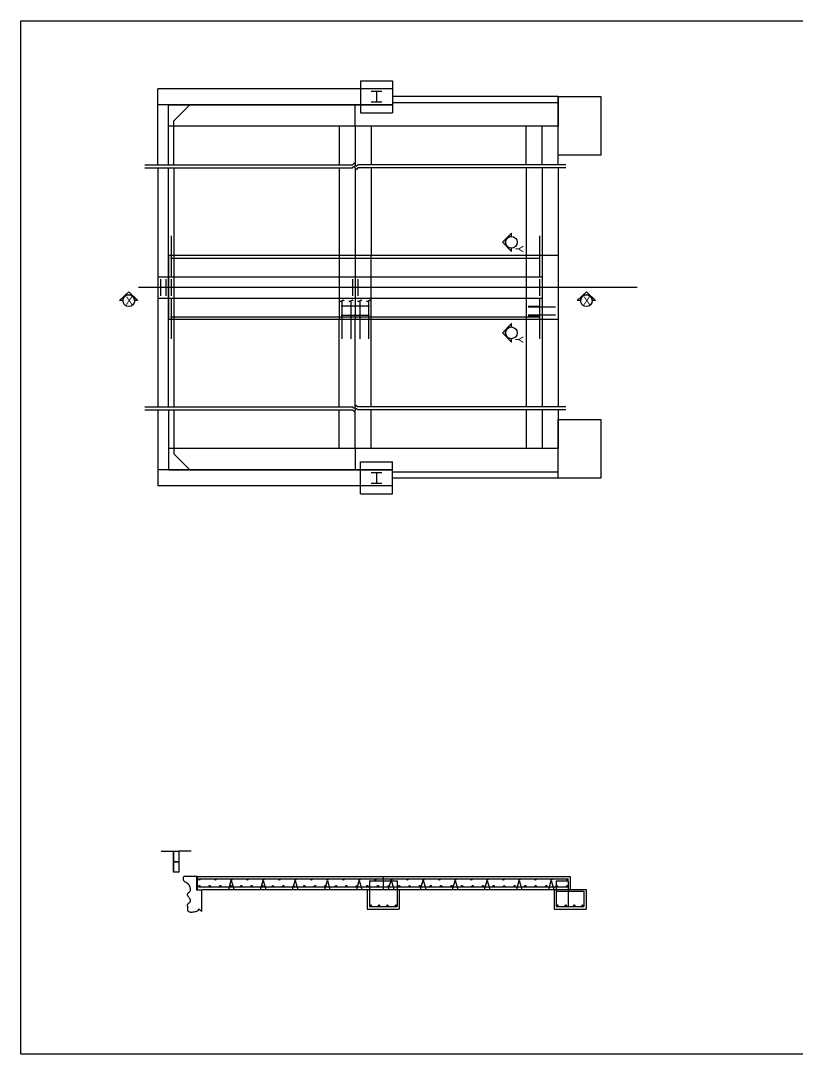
# Model space of a CAD drawing. Extents: x 1531 to 2925, y 1224 to 1658.
# Drawn here: x 2196.7 to 2269.3, y 1331.8 to 1428.7 of the extents above; entities that cross this region are included whole.
import ezdxf

# ---------------------------------------------------------------- set-up
doc = ezdxf.new("R2010")
doc.units = 0
for name, color, linetype in [('B_Border', 7, 'Continuous'), ('BD-EXIST-COSS', 7, 'Continuous'), ('BD-PROP-COSS', 7, 'Continuous'), ('BD-PROP-OSB', 7, 'Continuous'), ('D_FEMA A', 7, 'Continuous'), ('R_Border Prem', 7, 'Continuous'), ('R_Draft', 7, 'Continuous'), ('R_Guard Rail', 7, 'Continuous'), ('R_Road Edge of Shoulder', 7, 'Continuous'), ('R_Survey Control', 7, 'Continuous'), ('R_Wall', 7, 'Continuous')]:
    doc.layers.add(name, color=color, linetype=linetype)

msp = doc.modelspace()

# ---------------------------------------------------------------- linework, layer by layer
at = {"layer": 'B_Border'}
msp.add_line((2254.494, 1403.73), (2207.761, 1403.73), dxfattribs=at)
at = {"layer": 'BD-EXIST-COSS'}
for p, q in [((2210.833, 1408.563), (2210.833, 1404.73)), ((2245.333, 1408.563), (2245.333, 1404.73)), ((2210.75, 1406.48), (2245.417, 1406.48)), ((2209.833, 1404.511), (2209.833, 1402.949)), ((2210.333, 1404.511), (2210.333, 1402.949)), ((2210.833, 1404.511), (2210.833, 1402.949)), ((2227.833, 1404.511), (2227.833, 1402.949)), ((2228.333, 1404.511), (2228.333, 1402.949)), ((2245.333, 1404.511), (2245.333, 1402.949)), ((2210.833, 1402.73), (2210.833, 1398.897)), ((2226.833, 1402.465), (2226.833, 1398.897)), ((2227.667, 1402.465), (2227.667, 1398.897)), ((2228.5, 1402.465), (2228.5, 1398.897)), ((2229.333, 1402.465), (2229.333, 1398.897)), ((2245.333, 1402.73), (2245.333, 1398.897)), ((2229.417, 1401.98), (2226.75, 1401.98)), ((2244.292, 1401.98), (2245.375, 1401.98)), ((2244.292, 1401.897), (2246.833, 1401.897)), ((2244.292, 1401.164), (2246.833, 1401.164)), ((2210.75, 1400.98), (2245.417, 1400.98)), ((2229.417, 1401.08), (2226.75, 1401.08)), ((2244.292, 1401.08), (2245.375, 1401.08)), ((2213.373, 1348.288), (2248.039, 1348.288)), ((2229.414, 1348.108), (2231.998, 1348.108)), ((2229.414, 1348.108), (2229.414, 1345.705)), ((2231.998, 1348.108), (2231.998, 1345.705)), ((2246.914, 1348.108), (2248.025, 1348.108)), ((2246.914, 1348.108), (2246.914, 1345.702)), ((2248.025, 1348.108), (2248.025, 1345.702)), ((2213.373, 1347.538), (2248.039, 1347.538)), ((2246.914, 1347.121), (2249.498, 1347.121)), ((2249.498, 1347.121), (2249.498, 1345.705)), ((2229.414, 1345.705), (2231.998, 1345.705)), ((2246.914, 1345.705), (2249.498, 1345.705))]:
    msp.add_line(p, q, dxfattribs=at)
for centre, radius in [((2213.449, 1348.225), 0.063), ((2214.949, 1348.225), 0.063), ((2216.449, 1348.225), 0.063), ((2217.949, 1348.225), 0.063), ((2219.449, 1348.225), 0.063), ((2220.949, 1348.225), 0.063), ((2222.449, 1348.225), 0.063), ((2223.949, 1348.225), 0.063), ((2225.449, 1348.225), 0.063), ((2226.949, 1348.225), 0.063), ((2228.449, 1348.225), 0.063), ((2229.949, 1348.225), 0.063), ((2231.449, 1348.225), 0.063), ((2232.949, 1348.225), 0.063), ((2234.449, 1348.225), 0.063), ((2235.949, 1348.225), 0.063), ((2237.449, 1348.225), 0.063), ((2238.949, 1348.225), 0.063), ((2240.449, 1348.225), 0.063), ((2241.949, 1348.225), 0.063), ((2243.449, 1348.225), 0.063), ((2244.949, 1348.225), 0.063), ((2246.449, 1348.225), 0.063), ((2247.949, 1348.225), 0.063), ((2213.449, 1347.601), 0.063), ((2214.435, 1347.601), 0.063), ((2215.421, 1347.601), 0.063), ((2216.406, 1347.601), 0.063), ((2217.392, 1347.601), 0.063), ((2218.378, 1347.601), 0.063), ((2219.363, 1347.601), 0.063), ((2220.349, 1347.601), 0.063), ((2221.335, 1347.601), 0.063), ((2222.321, 1347.601), 0.063), ((2223.306, 1347.601), 0.063), ((2224.292, 1347.601), 0.063), ((2225.278, 1347.601), 0.063), ((2226.263, 1347.601), 0.063), ((2227.249, 1347.601), 0.063), ((2228.235, 1347.601), 0.063), ((2229.22, 1347.601), 0.063), ((2230.206, 1347.601), 0.063), ((2231.192, 1347.601), 0.063), ((2232.178, 1347.601), 0.063), ((2233.163, 1347.601), 0.063), ((2234.149, 1347.601), 0.063), ((2235.135, 1347.601), 0.063), ((2236.12, 1347.601), 0.063), ((2237.106, 1347.601), 0.063), ((2238.092, 1347.601), 0.063), ((2239.078, 1347.601), 0.063), ((2240.063, 1347.601), 0.063), ((2241.049, 1347.601), 0.063), ((2242.035, 1347.601), 0.063), ((2243.02, 1347.601), 0.063), ((2244.006, 1347.601), 0.063), ((2244.992, 1347.601), 0.063), ((2245.978, 1347.601), 0.063), ((2246.963, 1347.601), 0.063), ((2247.949, 1347.601), 0.063), ((2229.522, 1345.77), 0.0625), ((2230.311, 1345.77), 0.0625), ((2231.101, 1345.77), 0.0625), ((2231.89, 1345.77), 0.0625), ((2247.022, 1345.77), 0.0625), ((2247.811, 1345.77), 0.0625), ((2248.601, 1345.77), 0.0625), ((2249.39, 1345.77), 0.0625)]:
    msp.add_circle(centre, radius, dxfattribs=at)
for centre, start, end in [((2226.741, 1402.519), 185.21332, 329.73936), ((2226.926, 1402.411), 5.21239, 149.73919), ((2227.574, 1402.519), 185.21332, 329.73936), ((2227.759, 1402.411), 5.21239, 149.73919), ((2228.407, 1402.519), 185.21332, 329.73936), ((2228.593, 1402.411), 5.21239, 149.73919), ((2229.241, 1402.519), 185.21332, 329.73936), ((2229.426, 1402.411), 5.21239, 149.73919)]:
    msp.add_arc(centre, 0.107, start, end, dxfattribs=at)
at = {"layer": 'BD-PROP-COSS'}
for p, q in [((2211.037, 1350.873), (2211.537, 1350.873)), ((2213.248, 1348.496), (2213.206, 1348.496)), ((2230.706, 1348.496), (2230.706, 1347.288))]:
    msp.add_line(p, q, dxfattribs=at)
at = {"layer": 'BD-PROP-OSB'}
for p, q in [((2211.037, 1349.873), (2211.037, 1350.873)), ((2211.037, 1350.873), (2211.537, 1350.873)), ((2211.537, 1350.873), (2211.537, 1350.873)), ((2211.537, 1350.873), (2211.537, 1349.873)), ((2211.537, 1349.873), (2211.037, 1349.873)), ((2211.037, 1348.894), (2211.037, 1349.873)), ((2211.037, 1349.873), (2211.537, 1349.873)), ((2211.537, 1349.873), (2211.537, 1349.873)), ((2211.537, 1349.873), (2211.537, 1348.894)), ((2211.537, 1348.894), (2211.037, 1348.894)), ((2213.206, 1348.496), (2213.206, 1348.496)), ((2213.206, 1348.496), (2213.206, 1348.413)), ((2213.248, 1348.496), (2213.206, 1348.496)), ((2213.206, 1348.413), (2213.206, 1348.413)), ((2213.206, 1348.413), (2213.248, 1348.413)), ((2213.248, 1348.413), (2213.206, 1348.413)), ((2213.206, 1348.413), (2213.206, 1348.413)), ((2213.206, 1348.413), (2213.206, 1347.246)), ((2213.248, 1348.413), (2213.248, 1348.496)), ((2213.248, 1347.246), (2213.248, 1348.413)), ((2213.206, 1347.246), (2213.248, 1347.246)), ((2213.206, 1347.246), (2213.206, 1347.246))]:
    msp.add_line(p, q, dxfattribs=at)
at = {"layer": 'D_FEMA A'}
for p, q in [((2216.212, 1347.3), (2216.455, 1348.144)), ((2216.455, 1348.144), (2216.698, 1347.3)), ((2219.206, 1347.292), (2219.449, 1348.137)), ((2219.449, 1348.137), (2219.692, 1347.292)), ((2222.207, 1347.288), (2222.45, 1348.132)), ((2222.45, 1348.132), (2222.693, 1347.288)), ((2225.22, 1347.294), (2225.464, 1348.138)), ((2225.464, 1348.138), (2225.707, 1347.294)), ((2228.214, 1347.278), (2228.457, 1348.123)), ((2228.457, 1348.123), (2228.7, 1347.278)), ((2231.199, 1347.302), (2231.442, 1348.146)), ((2231.442, 1348.146), (2231.685, 1347.302)), ((2234.207, 1347.304), (2234.45, 1348.149)), ((2234.45, 1348.149), (2234.693, 1347.304)), ((2237.197, 1347.283), (2237.44, 1348.128)), ((2237.44, 1348.128), (2237.683, 1347.283)), ((2240.201, 1347.285), (2240.444, 1348.13)), ((2240.444, 1348.13), (2240.687, 1347.285)), ((2243.207, 1347.275), (2243.45, 1348.119)), ((2243.45, 1348.119), (2243.694, 1347.275)), ((2246.211, 1347.295), (2246.454, 1348.14)), ((2246.454, 1348.14), (2246.697, 1347.295))]:
    msp.add_line(p, q, dxfattribs=at)
at = {"layer": 'R_Border Prem'}
for p, q in [((2247.083, 1421.625), (2231.583, 1421.625)), ((2247.083, 1421.042), (2231.583, 1421.042)), ((2247.083, 1418.833), (2210.583, 1418.833)), ((2247.083, 1406.73), (2210.583, 1406.73)), ((2210.583, 1406.73), (2210.583, 1400.73)), ((2226.583, 1406.73), (2226.583, 1400.73)), ((2228.083, 1406.73), (2228.083, 1400.73)), ((2229.583, 1400.73), (2229.583, 1406.73)), ((2244.083, 1406.73), (2244.083, 1400.73)), ((2245.583, 1406.73), (2245.583, 1400.73)), ((2247.083, 1406.73), (2247.083, 1400.73)), ((2247.083, 1400.73), (2210.583, 1400.73)), ((2247.083, 1388.627), (2210.583, 1388.627)), ((2247.083, 1386.418), (2231.583, 1386.418)), ((2247.083, 1385.835), (2231.583, 1385.835)), ((2212.702, 1350.873), (2211.537, 1350.873)), ((2211.537, 1350.873), (2211.537, 1348.894)), ((2213.248, 1348.496), (2248.206, 1348.496)), ((2213.248, 1348.496), (2213.248, 1347.246)), ((2248.206, 1348.496), (2248.206, 1347.288)), ((2213.248, 1347.246), (2213.706, 1347.246)), ((2213.706, 1347.246), (2213.789, 1347.288)), ((2213.789, 1347.288), (2249.706, 1347.288)), ((2229.206, 1347.288), (2229.206, 1345.455)), ((2232.206, 1347.288), (2232.206, 1345.455)), ((2246.706, 1347.288), (2246.706, 1345.455)), ((2249.706, 1347.288), (2249.706, 1345.455)), ((2229.206, 1345.455), (2232.206, 1345.455)), ((2246.706, 1345.455), (2249.706, 1345.455))]:
    msp.add_line(p, q, dxfattribs=at)
for points in [[(2247.083, 1421.625), (2251.083, 1421.625), (2251.083, 1416.125), (2247.083, 1416.125)], [(2247.083, 1391.335), (2251.083, 1391.335), (2251.083, 1385.835), (2247.083, 1385.835)]]:
    msp.add_lwpolyline(points, close=True, dxfattribs=at)
at = {"layer": 'R_Draft'}
for p, q in [((2209.583, 1404.73), (2245.583, 1404.73)), ((2209.583, 1404.73), (2209.583, 1402.73)), ((2245.583, 1404.73), (2245.583, 1402.73)), ((2209.583, 1402.73), (2245.583, 1402.73))]:
    msp.add_line(p, q, dxfattribs=at)
at = {"layer": 'R_Guard Rail'}
for p, q in [((2228.583, 1423.083), (2231.583, 1423.083)), ((2228.583, 1423.083), (2228.583, 1422.333)), ((2231.583, 1423.083), (2231.583, 1422.333)), ((2231.583, 1422.333), (2209.583, 1422.333)), ((2209.583, 1415.226), (2209.583, 1422.333)), ((2228.583, 1422.333), (2228.583, 1420.833)), ((2230.583, 1422.083), (2229.583, 1422.083)), ((2230.083, 1422.083), (2230.083, 1421.083)), ((2231.583, 1422.333), (2231.583, 1420.833)), ((2247.083, 1421.625), (2247.083, 1418.833)), ((2231.583, 1420.833), (2209.583, 1420.833)), ((2210.583, 1420.833), (2231.583, 1420.833)), ((2210.583, 1415.226), (2210.583, 1420.833)), ((2212.583, 1420.833), (2211.083, 1419.333)), ((2228.083, 1418.833), (2228.083, 1420.833)), ((2228.583, 1420.833), (2228.583, 1420.083)), ((2230.583, 1421.083), (2229.583, 1421.083)), ((2231.583, 1420.833), (2231.583, 1420.083)), ((2228.583, 1420.083), (2231.583, 1420.083)), ((2211.083, 1415.226), (2211.083, 1419.333)), ((2226.583, 1418.833), (2226.583, 1415.226)), ((2228.083, 1418.833), (2228.083, 1415.226)), ((2229.583, 1418.833), (2229.583, 1415.226)), ((2244.083, 1415.226), (2244.083, 1418.833)), ((2245.583, 1415.226), (2245.583, 1418.833)), ((2247.083, 1415.226), (2247.083, 1418.833)), ((2209.583, 1414.926), (2209.583, 1392.534)), ((2210.583, 1406.73), (2210.583, 1414.926)), ((2210.583, 1392.534), (2210.583, 1414.926)), ((2211.083, 1414.926), (2211.083, 1392.534)), ((2226.583, 1414.926), (2226.583, 1406.73)), ((2228.083, 1414.926), (2228.083, 1406.73)), ((2229.583, 1414.926), (2229.583, 1406.73)), ((2244.083, 1414.926), (2244.083, 1406.73)), ((2245.583, 1414.926), (2245.583, 1406.73)), ((2247.083, 1414.926), (2247.083, 1406.73)), ((2210.583, 1392.534), (2210.583, 1400.73)), ((2226.583, 1392.534), (2226.583, 1400.73)), ((2228.083, 1392.534), (2228.083, 1400.73)), ((2229.583, 1392.534), (2229.583, 1400.73)), ((2244.083, 1400.73), (2244.083, 1392.534)), ((2245.583, 1400.73), (2245.583, 1392.534)), ((2247.083, 1400.73), (2247.083, 1392.534)), ((2209.583, 1392.234), (2209.583, 1385.127)), ((2210.583, 1392.234), (2210.583, 1386.627)), ((2211.083, 1392.234), (2211.083, 1388.127)), ((2226.583, 1388.627), (2226.583, 1392.234)), ((2228.083, 1388.627), (2228.083, 1392.234)), ((2229.583, 1388.627), (2229.583, 1392.234)), ((2244.083, 1392.234), (2244.083, 1388.627)), ((2245.583, 1392.234), (2245.583, 1388.627)), ((2247.083, 1392.234), (2247.083, 1388.627)), ((2228.083, 1388.627), (2228.083, 1386.627)), ((2247.083, 1385.835), (2247.083, 1388.627)), ((2212.583, 1386.627), (2211.083, 1388.127)), ((2231.583, 1386.627), (2209.583, 1386.627)), ((2210.583, 1386.627), (2231.583, 1386.627)), ((2228.583, 1387.377), (2231.583, 1387.377)), ((2228.583, 1386.627), (2228.583, 1387.377)), ((2228.583, 1385.127), (2228.583, 1386.627)), ((2231.583, 1386.627), (2231.583, 1387.377)), ((2231.583, 1385.127), (2231.583, 1386.627)), ((2229.583, 1386.377), (2230.583, 1386.377)), ((2230.083, 1386.377), (2230.083, 1385.377)), ((2231.583, 1385.127), (2209.583, 1385.127)), ((2228.583, 1384.377), (2228.583, 1385.127)), ((2229.583, 1385.377), (2230.583, 1385.377)), ((2231.583, 1384.377), (2231.583, 1385.127)), ((2228.583, 1384.377), (2231.583, 1384.377))]:
    msp.add_line(p, q, dxfattribs=at)
at = {"layer": 'R_Road Edge of Shoulder'}
for p, q in [((2209.873, 1350.873), (2211.037, 1350.873)), ((2211.037, 1350.873), (2211.037, 1348.894)), ((2213.206, 1348.496), (2212.007, 1348.496)), ((2213.706, 1345.216), (2213.706, 1347.246))]:
    msp.add_line(p, q, dxfattribs=at)
msp.add_open_spline([(2213.706, 1345.216), (2213.366, 1345.517), (2213.354, 1345.208), (2212.347, 1345.095), (2212.403, 1345.671), (2212.302, 1345.861), (2212.754, 1346.263), (2212.221, 1346.825), (2212.725, 1347.171), (2212.459, 1347.846), (2211.903, 1348.078), (2212.007, 1348.496)], degree=2, dxfattribs=at)
at = {"layer": 'R_Survey Control'}
for points in [[(2242.707, 1408.512), (2242.707, 1408.819), (2241.88, 1407.96), (2242.707, 1407.1), (2242.707, 1407.407)], [(2206.295, 1402.486), (2205.987, 1402.486), (2206.847, 1403.313), (2207.707, 1402.486), (2207.399, 1402.486)], [(2249.194, 1402.486), (2248.887, 1402.486), (2249.746, 1403.313), (2250.606, 1402.486), (2250.299, 1402.486)], [(2242.707, 1400.019), (2242.707, 1400.326), (2241.88, 1399.466), (2242.707, 1398.607), (2242.707, 1398.914)]]:
    msp.add_lwpolyline(points, dxfattribs=at)
for centre in [(2242.707, 1407.957), (2206.849, 1402.486), (2249.746, 1402.486), (2242.707, 1399.464)]:
    msp.add_circle(centre, 0.552, dxfattribs=at)
for centre, start, end in [((2242.707, 1407.96), 90, 270), ((2206.847, 1402.486), 0, 180), ((2249.746, 1402.486), 0, 180), ((2242.707, 1399.466), 90, 270)]:
    msp.add_arc(centre, 0.552, start, end, dxfattribs=at)
at = {"layer": 'R_Wall'}
for p, q in [((2208.361, 1415.226), (2227.833, 1415.226)), ((2208.361, 1414.926), (2227.833, 1414.926)), ((2228, 1415.393), (2227.833, 1415.226)), ((2228, 1415.093), (2227.833, 1414.926)), ((2228.167, 1415.06), (2228, 1415.393)), ((2228.167, 1414.76), (2228, 1415.093)), ((2228.333, 1415.226), (2228.167, 1415.06)), ((2228.333, 1414.926), (2228.167, 1414.76)), ((2247.806, 1415.226), (2228.333, 1415.226)), ((2247.806, 1414.926), (2228.333, 1414.926)), ((2208.361, 1392.534), (2227.833, 1392.534)), ((2227.833, 1392.534), (2228, 1392.367)), ((2228.167, 1392.701), (2228, 1392.367)), ((2228, 1392.067), (2228.167, 1392.401)), ((2228.333, 1392.534), (2228.167, 1392.701)), ((2228.333, 1392.234), (2228.167, 1392.401)), ((2247.806, 1392.534), (2228.333, 1392.534)), ((2208.361, 1392.234), (2227.833, 1392.234)), ((2227.833, 1392.234), (2228, 1392.067)), ((2247.806, 1392.234), (2228.333, 1392.234))]:
    msp.add_line(p, q, dxfattribs=at)
msp.add_lwpolyline([(2196.716, 1428.728), (2341.933, 1428.728), (2341.933, 1331.833), (2196.716, 1331.833)], close=True, dxfattribs=at)

# ---------------------------------------------------------------- texts
at = {"layer": 'R_Survey Control'}
for s, rotation, p in [('Y', 270, (2243.082, 1407.662)), ('X', 360, (2206.552, 1402.111)), ('X', 360, (2249.449, 1402.111)), ('Y', 270, (2243.082, 1399.168))]:
    msp.add_text(s, height=0.75, rotation=rotation, dxfattribs=at).set_placement(p)

doc.saveas('drawing.dxf')
